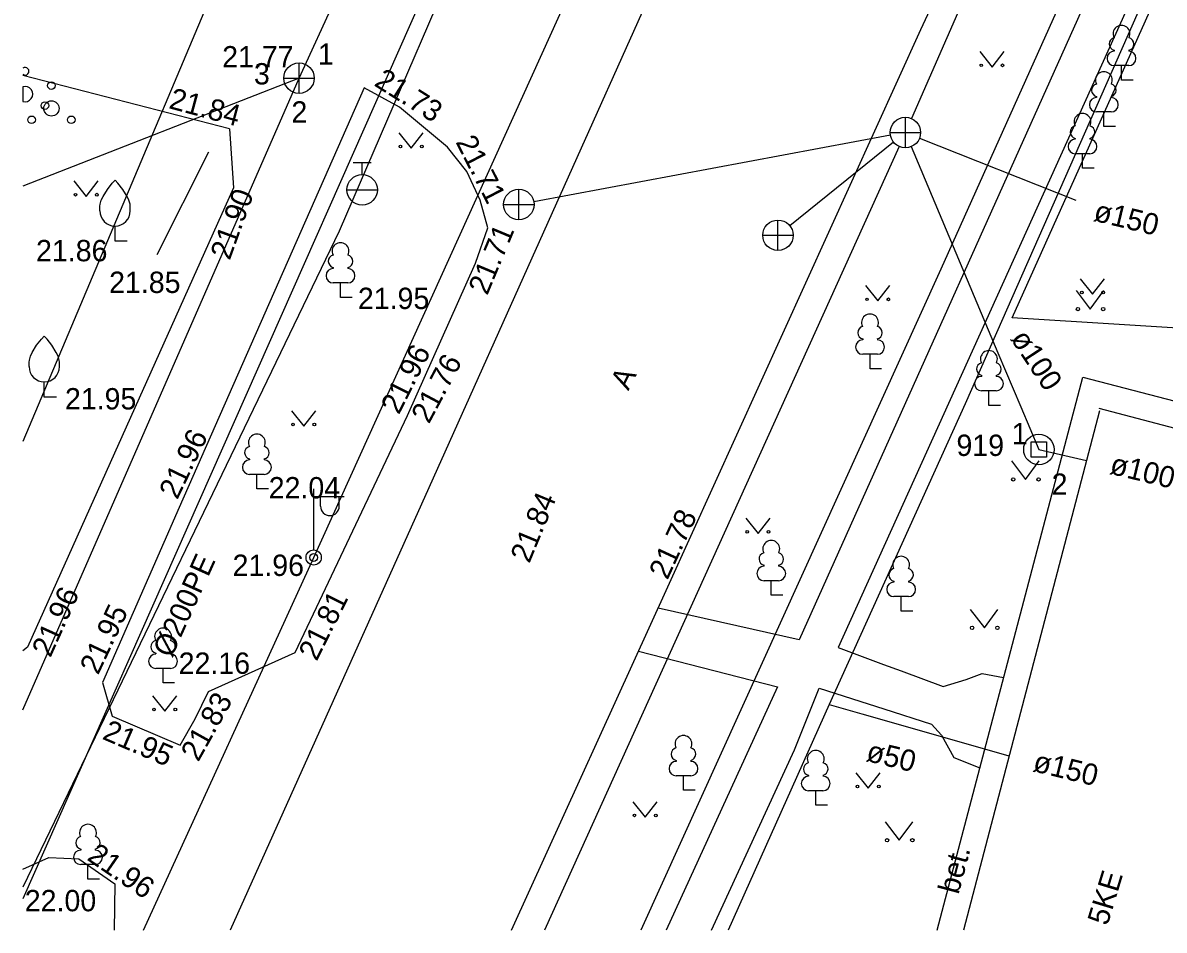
# Model space of a CAD drawing. Extents: x 714391 to 714584, y 6589993 to 6590151.
# Drawn here: x 714390.65 to 714428.09, y 6589992.71 to 6590022.48 of the extents above; entities that cross this region are included whole.
import ezdxf

# ---------------------------------------------------------------- set-up
doc = ezdxf.new("R2010")
doc.units = 0
for name, color, linetype in [('ABIJOONIS', 7, 'Continuous'), ('DKAEV', 7, 'Continuous'), ('HALJASTUS', 7, 'Continuous'), ('HOONE', 7, 'Continuous'), ('KAEVU_NR', 7, 'Continuous'), ('KKAEV', 7, 'Continuous'), ('KORGUS', 7, 'Continuous'), ('KPKAABEL', 7, 'Continuous'), ('KTRASS', 7, 'Continuous'), ('MPKAABEL', 7, 'Continuous'), ('POST', 7, 'Continuous'), ('PUU', 7, 'Continuous'), ('SITRASS', 7, 'Continuous'), ('SKTRASS', 7, 'Continuous'), ('TEE', 7, 'Continuous'), ('TORU NR', 7, 'Continuous'), ('VKAEV', 7, 'Continuous'), ('VTRASS', 7, 'Continuous'), ('Слой 1', 7, 'Continuous')]:
    doc.layers.add(name, color=color, linetype=linetype)

msp = doc.modelspace()

# ---------------------------------------------------------------- linework, layer by layer
at = {"layer": 'ABIJOONIS'}
msp.add_lwpolyline([(714413.426, 6590028.381), (714411.78, 6590024.65), (714403.97, 6590007.22), (714397.447, 6589992.711)], dxfattribs=at)
at = {"layer": 'DKAEV'}
for p, q in [((714423.73, 6590008.23), (714423.73, 6590008.73)), ((714423.73, 6590008.73), (714424.23, 6590008.73)), ((714424.23, 6590008.73), (714424.23, 6590008.23)), ((714424.23, 6590008.23), (714423.73, 6590008.23))]:
    msp.add_line(p, q, dxfattribs=at)
msp.add_circle((714423.98, 6590008.48), 0.5, dxfattribs=at)
at = {"layer": 'HALJASTUS'}
for p, q in [((714422.037, 6590021.535), (714422.442, 6590021.03)), ((714422.442, 6590021.03), (714422.837, 6590021.535)), ((714390.649, 6590020.379), (714390.649, 6590019.903)), ((714402.982, 6590018.871), (714403.387, 6590018.366)), ((714403.387, 6590018.366), (714403.782, 6590018.871)), ((714396.738, 6590018.236), (714395.043, 6590014.867)), ((714392.326, 6590017.291), (714392.731, 6590016.786)), ((714392.731, 6590016.786), (714393.126, 6590017.291)), ((714425.333, 6590014.085), (714425.738, 6590013.58)), ((714425.738, 6590013.58), (714426.133, 6590014.085)), ((714418.289, 6590013.859), (714418.694, 6590013.354)), ((714418.694, 6590013.354), (714419.089, 6590013.859)), ((714425.197, 6590013.697), (714425.66, 6590013.09)), ((714425.66, 6590013.09), (714426.106, 6590013.697)), ((714399.46, 6590009.75), (714399.865, 6590009.245)), ((714399.865, 6590009.245), (714400.26, 6590009.75)), ((714423.077, 6590008.107), (714423.54, 6590007.5)), ((714423.54, 6590007.5), (714423.986, 6590008.107)), ((714414.361, 6590006.228), (714414.766, 6590005.723)), ((714414.766, 6590005.723), (714415.161, 6590006.228)), ((714421.727, 6590003.237), (714422.19, 6590002.63)), ((714422.19, 6590002.63), (714422.636, 6590003.237)), ((714394.9, 6590000.403), (714395.305, 6589999.898)), ((714395.305, 6589999.898), (714395.7, 6590000.403)), ((714417.973, 6589997.875), (714418.378, 6589997.37)), ((714418.378, 6589997.37), (714418.773, 6589997.875)), ((714410.658, 6589996.926), (714411.063, 6589996.421)), ((714411.063, 6589996.421), (714411.458, 6589996.926)), ((714418.937, 6589996.267), (714419.4, 6589995.66)), ((714419.4, 6589995.66), (714419.846, 6589996.267))]:
    msp.add_line(p, q, dxfattribs=at)
for centre, radius in [((714422.089, 6590021.085), 0.0428), ((714422.789, 6590021.085), 0.0452), ((714391.588, 6590020.423), 0.125), ((714391.375, 6590019.766), 0.125), ((714391.588, 6590019.673), 0.25), ((714390.938, 6590019.298), 0.125), ((714392.238, 6590019.298), 0.125), ((714403.734, 6590018.421), 0.0452), ((714403.034, 6590018.421), 0.0428), ((714392.378, 6590016.841), 0.0428), ((714393.078, 6590016.841), 0.0452), ((714425.385, 6590013.635), 0.0428), ((714426.085, 6590013.635), 0.0452), ((714418.341, 6590013.409), 0.0428), ((714419.041, 6590013.409), 0.0452), ((714425.259, 6590013.09), 0.055), ((714426.088, 6590013.09), 0.055), ((714399.512, 6590009.3), 0.0428), ((714400.212, 6590009.3), 0.0452), ((714423.139, 6590007.5), 0.055), ((714423.968, 6590007.5), 0.055), ((714414.413, 6590005.778), 0.0428), ((714415.113, 6590005.778), 0.0452), ((714421.789, 6590002.63), 0.055), ((714422.618, 6590002.63), 0.055), ((714394.952, 6589999.954), 0.0428), ((714395.652, 6589999.954), 0.0452), ((714418.025, 6589997.425), 0.0428), ((714418.725, 6589997.425), 0.0452), ((714410.71, 6589996.477), 0.0428), ((714411.41, 6589996.477), 0.0452), ((714418.999, 6589995.66), 0.055), ((714419.828, 6589995.66), 0.055)]:
    msp.add_circle(centre, radius, dxfattribs=at)
for centre, radius, start, end in [((714390.725, 6590020.891), 0.125, 232.7813, 127.2187), ((714390.725, 6590020.141), 0.25, 252.3964, 107.6036)]:
    msp.add_arc(centre, radius, start, end, dxfattribs=at)
at = {"layer": 'HOONE'}
for points in [[(714459.73, 6590096.05), (714450.33, 6590074.44), (714440.46, 6590052.39), (714432.7, 6590035.24), (714421.56, 6590009.98), (714417.1, 6590000.12), (714413.783, 6589992.711)], [(714426.31, 6590016.21), (714426.268, 6590016.227)], [(714425.967, 6590009.745), (714421.506, 6589992.711)], [(714432.717, 6589992.711), (714436.467, 6590007.065), (714425.957, 6590009.825)], [(714423.98, 6590008.48), (714425.54, 6590008.12)], [(714417.1, 6590000.12), (714418.169, 6589999.813), (714418.751, 6589999.646), (714422.99, 6589998.43)]]:
    msp.add_lwpolyline(points, dxfattribs=at)
at = {"layer": 'KKAEV'}
for p, q in [((714399.709, 6590020.166), (714399.709, 6590021.166)), ((714399.209, 6590020.666), (714400.209, 6590020.666)), ((714419.6, 6590018.38), (714419.6, 6590019.38)), ((714419.1, 6590018.88), (714420.1, 6590018.88)), ((714406.92, 6590016.02), (714406.92, 6590017.02)), ((714406.42, 6590016.52), (714407.42, 6590016.52)), ((714415.42, 6590015.01), (714415.42, 6590016.01)), ((714414.92, 6590015.51), (714415.92, 6590015.51))]:
    msp.add_line(p, q, dxfattribs=at)
for centre in [(714399.709, 6590020.666), (714419.6, 6590018.88), (714406.92, 6590016.52), (714415.42, 6590015.51)]:
    msp.add_circle(centre, 0.5, dxfattribs=at)
at = {"layer": 'KPKAABEL'}
msp.add_lwpolyline([(714390.649, 6590090.709), (714391.22, 6590087.72), (714411.651, 6590078.699), (714417.543, 6590076.021), (714419.18, 6590075.27), (714445.64, 6590069.88), (714433.16, 6590042.04), (714420.76, 6590014.4), (714410.92, 6589992.711)], dxfattribs=at)
at = {"layer": 'KTRASS'}
for p, q in [((714399.709, 6590020.666), (714409.68, 6590042.435)), ((714399.709, 6590020.666), (714390.649, 6590017.123)), ((714390.649, 6589999.942), (714399.709, 6590020.666))]:
    msp.add_line(p, q, dxfattribs=at)
at = {"layer": 'MPKAABEL'}
msp.add_lwpolyline([(714394.611, 6589992.711), (714400.19, 6590004.938), (714412.114, 6590031.265), (714423.696, 6590056.183), (714434.84, 6590082.35), (714435.599, 6590083.495), (714435.59, 6590083.97), (714441.1, 6590097.08), (714442.02, 6590098.72), (714442.75, 6590099.35), (714444.22, 6590100.41), (714445.54, 6590101.3), (714446.63, 6590102.41), (714450.168, 6590111.053), (714453.153, 6590116.846), (714463.66, 6590139.57), (714466.53, 6590147), (714468.444, 6590151.075)], dxfattribs=at)
at = {"layer": 'POST'}
for p, q in [((714400.19, 6590005.188), (714400.19, 6590007.188)), ((714400.19, 6590006.938), (714401.19, 6590006.938)), ((714400.417, 6590006.617), (714400.417, 6590006.938)), ((714401.029, 6590006.617), (714401.029, 6590006.938)), ((714400.19, 6590004.938), (714400.19, 6590004.938))]:
    msp.add_line(p, q, dxfattribs=at)
for radius in [0.25, 0.127]:
    msp.add_circle((714400.19, 6590004.938), radius, dxfattribs=at)
msp.add_arc((714400.723, 6590006.617), 0.306, 180, 0, dxfattribs=at)
at = {"layer": 'PUU'}
for p, q in [((714426.45, 6590021.58), (714426.45, 6590021.55)), ((714426.93, 6590021.58), (714426.93, 6590021.55)), ((714426.93, 6590021.075), (714426.45, 6590021.075)), ((714426.69, 6590020.6), (714426.69, 6590021.075)), ((714427.07, 6590020.6), (714426.69, 6590020.6)), ((714425.87, 6590020.06), (714425.87, 6590020.03)), ((714426.35, 6590020.06), (714426.35, 6590020.03)), ((714426.35, 6590019.555), (714425.87, 6590019.555)), ((714426.11, 6590019.08), (714426.11, 6590019.555)), ((714426.49, 6590019.08), (714426.11, 6590019.08)), ((714425.17, 6590018.69), (714425.17, 6590018.66)), ((714425.65, 6590018.69), (714425.65, 6590018.66)), ((714425.65, 6590018.185), (714425.17, 6590018.185)), ((714425.41, 6590017.71), (714425.41, 6590018.185)), ((714425.79, 6590017.71), (714425.41, 6590017.71)), ((714393.675, 6590015.313), (714393.675, 6590015.813)), ((714394.075, 6590015.313), (714393.675, 6590015.313)), ((714400.831, 6590014.45), (714400.831, 6590014.42)), ((714401.311, 6590014.45), (714401.311, 6590014.42)), ((714401.311, 6590013.945), (714400.831, 6590013.945)), ((714401.071, 6590013.47), (714401.071, 6590013.945)), ((714401.451, 6590013.47), (714401.071, 6590013.47)), ((714418.2, 6590012.11), (714418.2, 6590012.08)), ((714418.68, 6590012.11), (714418.68, 6590012.08)), ((714418.68, 6590011.605), (714418.2, 6590011.605)), ((714418.44, 6590011.13), (714418.44, 6590011.605)), ((714418.82, 6590011.13), (714418.44, 6590011.13)), ((714391.353, 6590010.2), (714391.353, 6590010.7)), ((714422.1, 6590010.91), (714422.1, 6590010.88)), ((714422.58, 6590010.91), (714422.58, 6590010.88)), ((714422.58, 6590010.405), (714422.1, 6590010.405)), ((714422.34, 6590009.93), (714422.34, 6590010.405)), ((714391.753, 6590010.2), (714391.353, 6590010.2)), ((714422.72, 6590009.93), (714422.34, 6590009.93)), ((714398.087, 6590008.169), (714398.087, 6590008.139)), ((714398.567, 6590008.169), (714398.567, 6590008.139)), ((714398.567, 6590007.664), (714398.087, 6590007.664)), ((714398.327, 6590007.189), (714398.327, 6590007.664)), ((714398.707, 6590007.189), (714398.327, 6590007.189)), ((714414.96, 6590004.68), (714414.96, 6590004.65)), ((714415.44, 6590004.68), (714415.44, 6590004.65)), ((714415.44, 6590004.175), (714414.96, 6590004.175)), ((714415.2, 6590003.7), (714415.2, 6590004.175)), ((714419.22, 6590004.16), (714419.22, 6590004.13)), ((714419.7, 6590004.16), (714419.7, 6590004.13)), ((714415.58, 6590003.7), (714415.2, 6590003.7)), ((714419.7, 6590003.655), (714419.22, 6590003.655)), ((714419.46, 6590003.18), (714419.46, 6590003.655)), ((714419.84, 6590003.18), (714419.46, 6590003.18)), ((714395.01, 6590001.803), (714395.01, 6590001.773)), ((714395.49, 6590001.803), (714395.49, 6590001.773)), ((714395.49, 6590001.298), (714395.01, 6590001.298)), ((714395.25, 6590000.823), (714395.25, 6590001.298)), ((714395.63, 6590000.823), (714395.25, 6590000.823)), ((714412.08, 6589998.28), (714412.08, 6589998.25)), ((714412.56, 6589998.28), (714412.56, 6589998.25)), ((714412.56, 6589997.775), (714412.08, 6589997.775)), ((714412.32, 6589997.3), (714412.32, 6589997.775)), ((714416.42, 6589997.79), (714416.42, 6589997.76)), ((714416.9, 6589997.79), (714416.9, 6589997.76)), ((714412.7, 6589997.3), (714412.32, 6589997.3)), ((714416.9, 6589997.285), (714416.42, 6589997.285)), ((714416.66, 6589996.81), (714416.66, 6589997.285)), ((714417.04, 6589996.81), (714416.66, 6589996.81)), ((714392.547, 6589995.368), (714392.547, 6589995.338)), ((714393.027, 6589995.368), (714393.027, 6589995.338)), ((714393.027, 6589994.863), (714392.547, 6589994.863)), ((714392.787, 6589994.388), (714392.787, 6589994.863)), ((714393.167, 6589994.388), (714392.787, 6589994.388))]:
    msp.add_line(p, q, dxfattribs=at)
for points in [[(714393.175, 6590016.313), (714393.175, 6590016.463), (714393.185, 6590016.528), (714393.22, 6590016.658), (714393.28, 6590016.778), (714393.425, 6590017.013), (714393.585, 6590017.218), (714393.675, 6590017.313)], [(714394.175, 6590016.313), (714394.175, 6590016.463), (714394.165, 6590016.528), (714394.13, 6590016.658), (714394.07, 6590016.778), (714393.925, 6590017.013), (714393.765, 6590017.218), (714393.675, 6590017.313)], [(714390.853, 6590011.2), (714390.853, 6590011.35), (714390.863, 6590011.415), (714390.898, 6590011.545), (714390.958, 6590011.665), (714391.103, 6590011.9), (714391.263, 6590012.105), (714391.353, 6590012.2)], [(714391.853, 6590011.2), (714391.853, 6590011.35), (714391.843, 6590011.415), (714391.808, 6590011.545), (714391.748, 6590011.665), (714391.603, 6590011.9), (714391.443, 6590012.105), (714391.353, 6590012.2)]]:
    msp.add_lwpolyline(points, dxfattribs=at)
for centre, radius, start, end in [((714426.69, 6590022.12), 0.277, 332.5799, 207.4201), ((714426.5, 6590021.788), 0.212, 105.2441, 257.079), ((714426.88, 6590021.788), 0.212, 282.921, 74.7559), ((714426.453, 6590021.313), 0.237, 90, 270), ((714426.927, 6590021.313), 0.237, 270, 90), ((714426.11, 6590020.6), 0.277, 332.5799, 207.4201), ((714425.92, 6590020.268), 0.212, 105.2441, 257.079), ((714426.3, 6590020.268), 0.212, 282.921, 74.7559), ((714425.872, 6590019.793), 0.237, 90, 270), ((714426.347, 6590019.793), 0.237, 270, 90), ((714425.41, 6590019.23), 0.277, 332.5799, 207.4201), ((714425.22, 6590018.897), 0.212, 105.2441, 257.079), ((714425.6, 6590018.897), 0.212, 282.921, 74.7559), ((714425.172, 6590018.423), 0.237, 90, 270), ((714425.647, 6590018.423), 0.237, 270, 90), ((714393.675, 6590016.313), 0.5, 180, 0), ((714401.071, 6590014.99), 0.277, 332.5799, 207.4201), ((714400.881, 6590014.658), 0.212, 105.2441, 257.079), ((714401.261, 6590014.658), 0.212, 282.921, 74.7559), ((714400.833, 6590014.183), 0.237, 90, 270), ((714401.308, 6590014.183), 0.237, 270, 90), ((714418.44, 6590012.65), 0.277, 332.5799, 207.4201), ((714418.25, 6590012.317), 0.212, 105.2441, 257.079), ((714418.63, 6590012.317), 0.212, 282.921, 74.7559), ((714418.203, 6590011.843), 0.237, 90, 270), ((714418.677, 6590011.843), 0.237, 270, 90), ((714422.34, 6590011.45), 0.277, 332.5799, 207.4201), ((714391.353, 6590011.2), 0.5, 180, 0), ((714422.15, 6590011.118), 0.212, 105.2441, 257.079), ((714422.53, 6590011.118), 0.212, 282.921, 74.7559), ((714422.103, 6590010.643), 0.237, 90, 270), ((714422.578, 6590010.643), 0.237, 270, 90), ((714398.327, 6590008.709), 0.277, 332.5799, 207.4201), ((714398.137, 6590008.377), 0.212, 105.2441, 257.079), ((714398.517, 6590008.377), 0.212, 282.921, 74.7559), ((714398.09, 6590007.901), 0.237, 90, 270), ((714398.565, 6590007.901), 0.237, 270, 90), ((714415.2, 6590005.22), 0.277, 332.5799, 207.4201), ((714415.01, 6590004.888), 0.212, 105.2441, 257.079), ((714415.39, 6590004.888), 0.212, 282.921, 74.7559), ((714414.963, 6590004.413), 0.237, 90, 270), ((714415.438, 6590004.413), 0.237, 270, 90), ((714419.46, 6590004.7), 0.277, 332.5799, 207.4201), ((714419.27, 6590004.368), 0.212, 105.2441, 257.079), ((714419.65, 6590004.368), 0.212, 282.921, 74.7559), ((714419.223, 6590003.893), 0.237, 90, 270), ((714419.698, 6590003.893), 0.237, 270, 90), ((714395.25, 6590002.343), 0.277, 332.5799, 207.4201), ((714395.06, 6590002.01), 0.212, 105.2441, 257.079), ((714395.44, 6590002.01), 0.212, 282.921, 74.7559), ((714395.012, 6590001.535), 0.237, 90, 270), ((714395.487, 6590001.535), 0.237, 270, 90), ((714412.32, 6589998.82), 0.277, 332.5799, 207.4201), ((714412.13, 6589998.488), 0.212, 105.2441, 257.079), ((714412.51, 6589998.488), 0.212, 282.921, 74.7559), ((714412.083, 6589998.013), 0.237, 90, 270), ((714412.557, 6589998.013), 0.237, 270, 90), ((714416.66, 6589998.33), 0.277, 332.5799, 207.4201), ((714416.47, 6589997.998), 0.212, 105.2441, 257.079), ((714416.85, 6589997.998), 0.212, 282.921, 74.7559), ((714416.422, 6589997.523), 0.237, 90, 270), ((714416.897, 6589997.523), 0.237, 270, 90), ((714392.787, 6589995.908), 0.277, 332.5799, 207.4201), ((714392.597, 6589995.576), 0.212, 105.2441, 257.079), ((714392.977, 6589995.576), 0.212, 282.921, 74.7559), ((714392.549, 6589995.101), 0.237, 90, 270), ((714393.024, 6589995.101), 0.237, 270, 90)]:
    msp.add_arc(centre, radius, start, end, dxfattribs=at)
at = {"layer": 'SITRASS'}
msp.add_line((714402.789, 6590037.515), (714390.649, 6590008.74), dxfattribs=at)
at = {"layer": 'SKTRASS'}
for p, q in [((714437.189, 6590059.042), (714419.801, 6590019.338)), ((714419.108, 6590018.789), (714407.412, 6590016.611)), ((714419.211, 6590018.566), (714415.809, 6590015.824)), ((714420.065, 6590018.696), (714425.196, 6590016.667)), ((714419.394, 6590018.424), (714407.761, 6589992.711))]:
    msp.add_line(p, q, dxfattribs=at)
msp.add_lwpolyline([(714419.794, 6590018.419), (714422.634, 6590011.655), (714423.391, 6590009.879), (714423.98, 6590008.48)], dxfattribs=at)
at = {"layer": 'TEE'}
for points in [[(714406.684, 6589992.711), (714411.807, 6590003.978), (714420.103, 6590022.258), (714430.572, 6590044.696), (714436.708, 6590058.068)], [(714421.729, 6590025.744), (714426.54, 6590025.48), (714416.12, 6590002.24), (714411.487, 6590003.275)], [(714457.41, 6590021.74), (714456.97, 6590022.09), (714456.24, 6590022.77), (714455.28, 6590023.03), (714451.04, 6590023.38), (714437.45, 6590024.7), (714430.368, 6590025.27), (714429.927, 6590025.305), (714428, 6590025.46), (714417.4, 6590001.98), (714418.881, 6590001.433), (714419.464, 6590001.218), (714420.84, 6590000.71), (714421.59, 6590000.94), (714422.12, 6590001.13), (714422.82, 6590001)], [(714397.434, 6590019.004), (714390.649, 6590020.757)], [(714403.01, 6590019.712), (714401.847, 6590020.342), (714395.777, 6590006.579), (714393.258, 6590000.833), (714393.582, 6589999.734), (714395.806, 6589998.776)], [(714395.806, 6589998.776), (714396.299, 6589999.646), (714396.744, 6590000.547), (714399.586, 6590001.821), (714403.267, 6590009.601), (714405.502, 6590014.591), (714405.898, 6590015.751), (714405.646, 6590016.666), (714405.214, 6590017.598), (714404.577, 6590018.402), (714403.01, 6590019.712)], [(714397.434, 6590019.004), (714397.56, 6590017.067), (714390.801, 6590002.001), (714390.649, 6590001.877)], [(714420.637, 6589992.711), (714425.417, 6590010.855), (714437.497, 6590007.715), (714435.197, 6589998.595), (714436.747, 6589998.085), (714435.586, 6589992.711)], [(714410.846, 6590001.864), (714415.4, 6590000.7), (714411.749, 6589992.711)], [(714413.243, 6589992.711), (714415.96, 6589998.63), (714416.77, 6590000.65), (714418.376, 6590000.137), (714418.898, 6589999.97), (714420.46, 6589999.47), (714420.78, 6589999.11), (714421.19, 6589998.38), (714422.04, 6589998.04)], [(714390.649, 6589994.71), (714391.503, 6589995.097), (714392.488, 6589995.05), (714393.667, 6589994.229), (714393.644, 6589992.711)]]:
    msp.add_lwpolyline(points, dxfattribs=at)
at = {"layer": 'VKAEV'}
for p, q in [((714401.481, 6590017.902), (714402.081, 6590017.902)), ((714401.781, 6590017.502), (714401.781, 6590017.902)), ((714401.281, 6590017.002), (714402.281, 6590017.002))]:
    msp.add_line(p, q, dxfattribs=at)
msp.add_circle((714401.781, 6590017.002), 0.5, dxfattribs=at)
at = {"layer": 'VTRASS'}
msp.add_line((714410.83, 6590039.297), (714390.649, 6589993.74), dxfattribs=at)
msp.add_lwpolyline([(714413.224, 6590043.919), (714411.375, 6590039.633), (714401.025, 6590015.647), (714390.649, 6589994.119)], dxfattribs=at)
at = {"layer": 'Слой 1'}
msp.add_lwpolyline([(714455.78, 6590085.63), (714478.99, 6590085.97), (714478.28, 6590068.22), (714475.39, 6590009.54), (714423.1, 6590012.8)], close=True, dxfattribs=at)

# ---------------------------------------------------------------- texts
at = {"layer": 'HOONE'}
msp.add_text('5KE', height=0.7, rotation=73.0864, dxfattribs=at).set_placement((714426.227, 6589992.834))
at = {"layer": 'KAEVU_NR'}
msp.add_text('919', height=0.7, dxfattribs=at).set_placement((714421.275, 6590008.27))
at = {"layer": 'KORGUS'}
for s, p in [('21.77', (714397.188, 6590021.017)), ('21.86', (714391.083, 6590014.657)), ('21.85', (714393.48, 6590013.617)), ('21.95', (714401.64, 6590013.09)), ('21.95', (714392.031, 6590009.796)), ('22.04', (714398.715, 6590006.877)), ('21.96', (714397.53, 6590004.333)), ('22.16', (714395.762, 6590001.121)), ('22.00', (714390.714, 6589993.331))]:
    msp.add_text(s, height=0.7, dxfattribs=at).set_placement(p)
for s, rotation, p in [('21.73', 327.6526, (714402.14, 6590020.439)), ('21.84', 344.976, (714395.41, 6590019.684)), ('21.71', 297.0127, (714404.835, 6590018.572)), ('21.90', 70.0169, (714397.435, 6590014.665)), ('21.71', 67.3532, (714405.884, 6590013.515)), ('21.96', 63.1131, (714402.984, 6590009.6)), ('21.76', 61.9275, (714403.971, 6590009.297)), ('21.96', 64.2092, (714395.716, 6590006.813)), ('21.84', 67.4515, (714407.263, 6590004.722)), ('21.78', 65.0952, (714411.794, 6590004.178)), ('21.96', 65.761, (714391.554, 6590001.629)), ('21.81', 63.3011, (714400.287, 6590001.512)), ('21.95', 64.7143, (714393.119, 6590001.06)), ('21.83', 60.7945, (714396.405, 6589998.208)), ('21.95', 336.6357, (714393.225, 6589998.996)), ('21.96', 325.4322, (714392.722, 6589995.036))]:
    msp.add_text(s, height=0.7, rotation=rotation, dxfattribs=at).set_placement(p)
at = {"layer": 'TEE'}
for s, rotation, p in [('A', 62.8402, (714410.513, 6590010.391)), ('bet.', 75.1254, (714421.341, 6589993.861))]:
    msp.add_text(s, height=0.7, rotation=rotation, dxfattribs=at).set_placement(p)
at = {"layer": 'TORU NR'}
for s, p in [('1', (714400.33, 6590021.105)), ('3', (714398.23, 6590020.458)), ('2', (714399.46, 6590019.206))]:
    msp.add_text(s, height=0.7, dxfattribs=at).set_placement(p)
for s, rotation, p in [('ø150', 346.3104, (714425.739, 6590015.995)), ('ø100', 303.4562, (714423.029, 6590012.121)), ('1', 359.9788, (714423.088, 6590008.655)), ('ø100', 346.3104, (714426.269, 6590007.695)), ('2', 359.9788, (714424.397, 6590006.995)), ('ø50', 346.3104, (714418.277, 6589998.271)), ('ø150', 346.3104, (714423.749, 6589997.935))]:
    msp.add_text(s, height=0.7, rotation=rotation, dxfattribs=at).set_placement(p)
at = {"layer": 'VTRASS'}
msp.add_text(' %%c200PE', height=0.7, rotation=65.6946, dxfattribs=at).set_placement((714395.42, 6590001.379))

doc.saveas('drawing.dxf')
